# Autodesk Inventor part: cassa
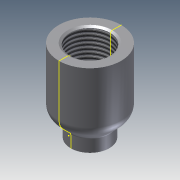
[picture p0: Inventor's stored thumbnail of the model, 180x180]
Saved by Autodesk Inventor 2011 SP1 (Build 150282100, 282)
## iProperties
Created: 2014-01
Part Number: cassa
Document SubType Name: Modeling
Designer: UTENTE
Density: 1 g/cm^3
Author: UTENTE
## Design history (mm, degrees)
sketch "Schizzo1"
  geometry: C1 r 9 at (0, 0); 1 further point
  constraints: 1 centre point, 1 coincident
extrude "Estrusione1" new body sketch "Schizzo1" distance "d1" = 6; taper "d2" = 0 deg
sketch "Schizzo2"
  geometry: C1 r 9 at (0, 0) reference; C2 r 14.5 at (0, 0)
  constraints: 1 centre point, 1 coincident
extrude "Estrusione2" join sketch "Schizzo2" distance "d4" = 32; taper "d5" = 0 deg
sketch "Schizzo3"
  geometry: C1 r 9 at (0, 0) reference; C2 r 6 at (0, 0)
  constraints: 1 centre point, 1 coincident
extrude "Estrusione3" cut sketch "Schizzo3" distance "d7" = 13; taper "d8" = 0 deg
sketch "Schizzo4"
  geometry: C1 r 6 at (0, 0) reference; C2 r 11 at (0, 0)
  constraints: 1 centre point, 1 coincident
extrude "Estrusione4" cut sketch "Schizzo4" distance "d10" = 11; taper "d11" = 0 deg
hole "Hole1" diameter "d14" = 18.631; stored, may be unused: countersink angle "d18" = 90 deg, drill point angle "d20" = 118 deg; dims "d12" = 10, "d13" = 10, "d15" = 6, "d16" = 4, "d17" = 2, "d19" = 23
chamfer "Smusso1" distance "d21" = 0.5; stored, may be unused: second distance "d22" = 2, angle "d23" = 45 deg
fillet "Raccordo1" dims "d24" = 2
chamfer "Smusso2" distance "d25" = 1; stored, may be unused: second distance "d26" = 2, angle "d27" = 30 deg
chamfer "Smusso3" distance "d28" = 5.5; stored, may be unused: second distance "d29" = 2, angle "d30" = 45 deg
fillet "Raccordo2" dims "d31" = 6
fillet "Raccordo3" dims "d32" = 1
sketch "Schizzo5"
  geometry: L1 (-10.316, 38)-(-9.316, 37.423) reference; L2 (-9.316, 37.423)-(-9.316, 24) reference; L3 (-11, 22.025)-(-11, 15) reference; L4 (-9, 13)-(-6.5, 13) reference; L5 (-6.5, 13)-(-6, 12.5) reference; L6 (-6, 12.5)-(-6, 0) reference; L7 (-6, 0)-(-9, 0) reference; L8 (-9, 0)-(-9, 5.586) reference; L9 (-9.293, 6.293)-(-12.743, 9.743) reference; L10 (-14.5, 13.985)-(-14.5, 38) reference; L11 (-14.5, 38)-(-10.316, 38) reference; L12 (9.316, 37.423)-(10.316, 38) reference; L13 (10.316, 38)-(14.5, 38) reference; L14 (14.5, 38)-(14.5, 13.985) reference; L15 (12.743, 9.743)-(9.293, 6.293) reference; L16 (9, 5.586)-(9, 0) reference; L17 (9, 0)-(6, 0) reference; L18 (6, 0)-(6, 12.5) reference; L19 (6, 12.5)-(6.5, 13) reference; L20 (6.5, 13)-(9, 13) reference; L21 (11, 15)-(11, 22.025) reference; L22 (9.316, 24)-(9.316, 37.423) reference; A1 r 2 centre (-9, 22.025) between (-9.316, 24) and (-11, 22.025) reference; A2 r 2 centre (-9, 15) between (-11, 15) and (-9, 13) reference; A3 r 1 centre (-10, 5.586) between (-9, 5.586) and (-9.293, 6.293) reference; A4 r 6 centre (-8.5, 13.985) between (-14.5, 13.985) and (-12.743, 9.743) reference; A5 r 6 centre (8.5, 13.985) between (12.743, 9.743) and (14.5, 13.985) reference; A6 r 1 centre (10, 5.586) between (9.293, 6.293) and (9, 5.586) reference; A7 r 2 centre (9, 15) between (9, 13) and (11, 15) reference; A8 r 2 centre (9, 22.025) between (11, 22.025) and (9.316, 24) reference; 1 further point
  node "Proietta spigoli di taglio1"
node "Solido1"
